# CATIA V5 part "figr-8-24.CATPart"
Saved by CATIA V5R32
Part number: Part1
Bounding box of the stored display mesh (mm): x -50 to 50, y -62.5 to 62.5, z 0 to 10
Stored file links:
  D:\PROJECTS\Project 2022\CATIA V5 6R 2022\Resources\Part Files\c08_catia_v5_6r2022_prt\figr-8-24.CATPart
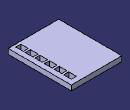
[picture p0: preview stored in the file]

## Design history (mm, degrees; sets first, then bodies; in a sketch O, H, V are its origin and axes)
Body1 (main body)
  Sketch1 on xy-plane, origin (0, 0, 0), H (1, 0, 0), V (0, 1, 0)
    line L1 (-50, 62.5) -> (50, 62.5)
    line L2 (50, 62.5) -> (50, -62.5)
    line L3 (50, -62.5) -> (-50, -62.5)
    line L4 (-50, -62.5) -> (-50, 62.5)
    axis line L5 (50, -62.5) -> (-50, 62.5)
    length L3 = 100
    length L2 = 125
    horizontal: L1 H, L3 H
    vertical: L2 V, L4 V
    midpoint: O L5
  Pad1: profile Sketch1, direction (0, 0, 1), length 10
  Sketch2 on face of Pad1, origin (0, 0, 10), H (1, 0, 0), V (0, 1, 0)
    line L1 (40, -57.5) -> (30, -57.5)
    line L2 (30, -57.5) -> (30, -42.5)
    line L3 (30, -42.5) -> (40, -42.5)
    line L4 (40, -42.5) -> (40, -57.5)
    reference projected line E1 (-50, -62.5) -> (50, -62.5) from edge [face of Pad1 | face of Pad1]
    reference projected line E2 (50, -62.5) -> (50, 62.5) from edge [face of Pad1 | face of Pad1]
    length L1 = 10
    length L4 = 15
    distance L1 E1 = 5
    distance L4 E2 = 10
    horizontal: L1 H, L3 H
    vertical: L2 V, L4 V
  Pocket1: profile Sketch2, direction (0, 0, -1), through (limit type 3)
  RectPattern1: of Pocket1, direction 1 instances 6, spacing 19, along edge [face of Pad1 | face of Pad1], direction 2 instances 6, spacing 15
